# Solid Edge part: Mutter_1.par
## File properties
Sűrűség: 0,000 kg/m^3
Pontosság: 0,990
Author: ahadarics
Last saved by: ahadarics
Revision: 77
Username: ahadarics
Dokumentum tartalom típus: 0
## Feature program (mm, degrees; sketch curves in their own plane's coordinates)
base feature "unnamed BaseFeature 1"
thread "unnamed Thread 1"
chamfer "Letörés_1"  SetBackValue2 = 60 deg
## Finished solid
Body 1: solid body, 23 faces, 46 edges, 24 vertices.
  Faces by surface: cone 14, plane 8, cylinder 1
  Edges by curve: spline 24, circle 16, line 6
Bounding box of the edges (mm): 5.000 x 15.011 x 13.000, from (0, -7.5056, -6.5) to (5, 7.5056, 6.5).
Cylindrical faces by radius (mm): R3.3235 x1
Conical faces (half-angle, radius in mm at the cone's reference point): 60 deg R3.3235 x1, 60 deg R4.0163 x1, 60 deg R7.0028 x12
Planar faces by outward normal: +x 1, +z 1, -x 1, -z 1, oblique 4
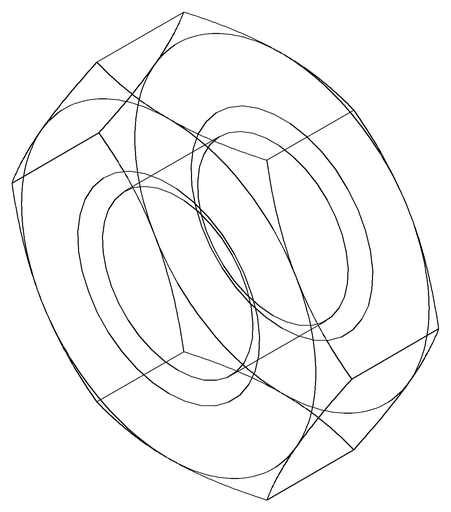
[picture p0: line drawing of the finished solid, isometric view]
